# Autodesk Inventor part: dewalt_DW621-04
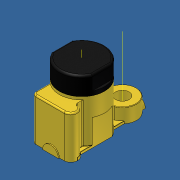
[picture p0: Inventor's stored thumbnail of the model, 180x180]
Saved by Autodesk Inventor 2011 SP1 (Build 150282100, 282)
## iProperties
Created: 2011-02
Part Number: dewalt_DW621-04
Material: Kst - PA6.6(Nylon)
Catalog Web Link: www.mittelmeyer.de
Document SubType Name: Modellieren
Designer: TMT
Manufacturer: Standard
Standards Organization: Custom
Density: 1.13 g/cm^3
Author: TMT
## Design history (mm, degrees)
sketch "Skizze2"
  geometry: L1 (-40.5, 85)-(40.5, 85); L2 (40.5, 85)-(40.5, -85); L3 (40.5, -85)-(-40.5, -85); L4 (-40.5, -85)-(-40.5, 85); L5 (0, -119)-(0, 119) reference; L6 (-56.7, 0)-(56.7, 0) reference
  constraints: 8 end point, 2 parallel, 1 horizontal, 1 perpendicular, 2 other
  dimensions: "d4" = 170 distance of L3.end L1.start (= laenge_01); "d5" = 81 distance of L2.end L3.end (= breite_01)
extrude "Extrusion2" new body sketch "Skizze2" distance "d6" = 5 (= hoehe_01); taper "d7" = 0 deg
workplane "Arbeitsebene1"
sketch "Skizze3"
  geometry: L1 (-40.5, -85)-(-40.5, 85) reference; L2 (40.5, -85)-(-40.5, -85) reference; L3 (-30.223, -85)-(-30.223, -45.277); L4 (-30.223, -45.277)-(-40.5, -35); L5 (56.7, -15)-(-56.7, -15) reference; 1 further point
  constraints: 4 end point, 2 point on line, 1 perpendicular
  dimensions: "d8" = 10.27713 distance between parallel lines of L3 L1; "d9" = 45 deg angle of L4 L2; "d11" = 20 distance from line of L4.end L5
extrude "Extrusion3" cut sketch "Skizze3" stored distance "d12" = 42.5; taper "d13" = 0 deg
sketch "Skizze4"
  geometry: L1 (40.5, -85)-(47.5, -85); L2 (47.5, -85)-(47.5, -59); L3 (47.5, -59)-(40.5, -59); L4 (40.5, -59)-(40.5, -85); 1 further point
  constraints: 8 end point, 2 parallel, 1 horizontal, 1 perpendicular
  dimensions: "d14" = 7 distance of L1.start L1.end; "d15" = 26 distance of L1.end L2.end
extrude "Extrusion4" join sketch "Skizze4" stored distance "d16" = 10; taper "d17" = 0 deg
fillet "Rundung3" dims "d18" = 13
fillet "Rundung4" dims "d19" = 8
sketch "Skizze5"
  geometry: L1 (40.5, 85)-(40.5, -59) reference; L2 (-40.5, 85)-(40.5, 85) reference; L3 (-40.5, -35)-(-30.223, -45.277) reference; L4 (30.5, 85)-(30.5, 15); L5 (30.5, 15)-(40.5, 5); L6 (65.1, -15)-(-58.1, -15) reference; 1 further point
  constraints: 4 end point, 2 parallel, 2 point on line
  dimensions: "d20" = 45 deg angle of L5 L2 (derived); "d21" = 20 distance from line of L5.end L6; "d22" = 10 distance between parallel lines of L1 L4
extrude "Extrusion5" cut sketch "Skizze5" stored distance "d23" = 30.25; taper "d24" = 0 deg
sketch "Skizze6"
  geometry: L1 (-40.5, 85)-(30.5, 85) reference; L2 (65.1, -15)-(-58.1, -15) reference; L3 (0, -119)-(0, 119) reference; C1 r 28 at (9, 57); 1 further point
  constraints: 1 centre point, 1 tangent
  dimensions: "d25" = 72 distance from line of C1.centre L2; "d26" = 9 distance from line of L3 C1.centre
extrude "Extrusion6" join sketch "Skizze6" stored distance "d27" = 3.75; taper "d28" = 0 deg
sketch "Skizze7"
  geometry: L1 (-40.5, 85)-(30.5, 85) reference; L2 (-40.5, -35)-(-40.5, 85) reference; L3 (-30.223, -45.277)-(-30.223, -77) reference; L4 (40.5, 5)-(30.5, 15) reference; L5 (-40.5, 5)-(-30.223, 15.277); L6 (-30.223, 15.277)-(-30.223, 85); 1 further point
  constraints: 4 end point, 2 perpendicular, 2 point on line, 1 collinear
  dimensions: "d29" = 45 deg angle of L5 L1 (derived); "d30" = 40 distance of L5.start L2.start
extrude "Extrusion7" cut sketch "Skizze7" stored distance "d31" = 42.75; taper "d32" = 0 deg
sketch "Skizze8"
  geometry: L1 (-30.223, 15.277)-(-40.5, 5) reference; L2 (-40.5, -35)-(-40.5, 5) reference; L3 (30.5, 74.937)-(30.5, 85) reference; L4 (-30.223, 85)-(-30.223, 15.277) reference; L5 (-37.5, 8)-(-44.813, 41.204); L6 (-38.721, 50.738)-(-30.223, 52.609); L7 (-45, 42.925)-(-45, 106.002); L8 (37, 57)-(37, 122.341); A1 r 28 centre (9, 57) between (30.5, 39.063) and (30.5, 74.937) reference; A2 r 8 centre (-37, 42.925) between (-38.721, 50.738) and (-44.813, 41.204); 1 further point
  constraints: 8 end point, 4 point on circle, 4 tangent, 2 parallel, 2 point on line, 1 centre point, 1 perpendicular
  dimensions: "d34" = 8 radius of A2; "d35" = 82 distance between parallel lines of L8 L7; "d36" = 3 distance from line of L5.start L2; "d37" = 42 distance from line of L5.start L6
extrude "Extrusion8" join sketch "Skizze8" stored distance "d38" = 3.75; taper "d39" = 0 deg
sketch "Skizze9"
  geometry: L1 (30.5, 74.937)-(30.5, 85) reference; L2 (-30.223, 85)-(30.5, 85) reference; L3 (9, 85)-(30.5, 85); L4 (30.5, 85)-(30.5, 74.937); A1 r 28 centre (9, 57) between (30.5, 39.063) and (30.5, 74.937) reference; A2 r 28 centre (9, 57) between (30.5, 74.937) and (9, 85); 1 further point
  constraints: 4 end point, 2 collinear, 2 point on circle, 1 centre point, 1 coincident, 1 tangent
extrude "Extrusion9" cut sketch "Skizze9" stored distance "d40" = 31.25; taper "d41" = 0 deg
sketch "Skizze20"
  geometry: L1 (-37.5, 8)-(-40.5, 5) reference; L2 (-40.5, -35)-(-40.5, 5) reference; L3 (-40.5, -35)-(-30.223, -45.277) reference; L4 (40.5, 5)-(40.5, -59) reference; L5 (66, -15)-(-63.5, -15) reference; L6 (-40.5, -15)-(40.5, -15); A1 r 45.169 centre (0, -15) between (-40.5, -35) and (40.5, -35); A2 r 45.169 centre (0, -15) between (40.5, 5) and (-40.5, 5); 1 further point
  constraints: 6 point on line, 5 point on circle, 3 end point, 2 centre point, 2 midpoint
extrude "Extrusion15" join sketch "Skizze20" stored distance "d87" = 10; taper "d88" = 0 deg
sketch "Skizze21"
  geometry: 1 further point
sketch "Skizze22"
  geometry: A1 r 45.169 centre (0, -15) between (-40.5, -35) and (-30.223, -48.568) reference; 2 further points
  constraints: 1 coincident, 3 other
extrude "Extrusion16" join sketch "Skizze22" distance "d89" = 90; taper "d90" = 0 deg
sketch "Skizze23"
  geometry: C1 r 45.169 at (0, 0) reference; 1 further point
extrude "Extrusion17" join sketch "Skizze23" distance "d91" = 32; taper "d92" = 0 deg
sketch "Skizze24"
  geometry: L1 (40.5, 20)-(40.5, -44) reference; L2 (-40.5, -20)-(-40.5, 20) reference; L3 (40.5, 20)-(40.5, -20); A1 r 45.169 centre (0, 0) between (40.5, 20) and (-40.5, -20) reference; 1 further point
  constraints: 2 end point, 1 point on circle, 1 point on line
extrude "Extrusion18" cut sketch "Skizze24" distance "d93" = 28; taper "d94" = 0 deg
sketch "Skizze25"
  geometry: L1 (-40.5, 5)-(-40.5, -35) reference; L2 (40.5, -35)-(40.5, 5) reference; A1 r 45.169 centre (0, -15) between (-40.5, 5) and (-40.5, -35) reference; A2 r 45.169 centre (0, -15) between (40.5, -35) and (40.5, 5) reference; 1 further point
extrude "Extrusion19" cut sketch "Skizze25" distance "d95" = 48; taper "d96" = 0 deg
sketch "Skizze26"
  geometry: L1 (-30.223, -48.568)-(-30.223, -77) reference; L2 (34.5, -85)-(-22.223, -85) reference; L3 (40.5, -35)-(40.5, -59) reference; L4 (32.5, -46.369)-(32.5, -59.155); A1 r 45.169 centre (0, -15) between (-30.223, -48.568) and (40.5, -35) reference; A2 r 8 centre (-22.223, -77) between (-30.223, -77) and (-22.223, -85) reference; A3 r 13 centre (34.5, -72) between (34.5, -85) and (47.5, -72) reference; A4 r 13 centre (34.5, -72) between (34.5, -85) and (32.5, -59.155); 1 further point
  constraints: 3 end point, 3 point on circle, 1 centre point, 1 coincident, 1 parallel
  dimensions: "d97" = 8 distance between parallel lines of L3 L4
extrude "Extrusion20" join sketch "Skizze26" distance "d98" = 80; taper "d99" = 0 deg
sketch "Skizze27"
  geometry: L1 (-30.223, 85)-(-30.223, 52.609) reference; L2 (-1.392, 31)-(19.392, 31); A1 r 28 centre (9, 57) between (30.5, 39.063) and (9, 85) reference; A2 r 28 centre (9, 57) between (19.392, 31) and (-1.392, 31); 1 further point
  constraints: 2 end point, 2 point on circle, 1 centre point, 1 coincident, 1 concentric, 1 perpendicular
  dimensions: "d100" = 26 distance from line of L2 A2.centre
extrude "Extrusion21" join sketch "Skizze27" distance "d101" = 24; taper "d102" = 0 deg
sketch "Skizze28"
  geometry: L1 (-30.223, 52.609)-(-38.721, 50.738) reference; L2 (-44.813, 41.204)-(-37.86, 9.635) reference; 2 further points
  dimensions: "d103" = 14 distance from line of point (-29.85, 38.356) L2; "d104" = 14 distance from line of point (-29.85, 38.356) L1
hole "Hole4" sketch "Skizze28" at (-29.85, 38.356) diameter "d105" = 12; stored, may be unused: countersink angle "d109" = 90 deg, drill point angle "d111" = 118 deg; dims "d106" = 6, "d107" = 4, "d108" = 2, "d110" = 8
workaxis "Arbeitsachse1"
sketch "Skizze29"
  geometry: L1 (-4.669, 99)-(-4.669, 53) reference; L2 (-4.669, 91.268)-(-3.669, 91); L3 (-3.669, 91)-(-4.669, 90.732); L4 (-3.669, 91)-(-4.669, 91); L5 (0, 127)-(81, 127) reference; L6 (40.5, 152.4)-(40.5, -25.4) reference; 1 further point
  constraints: 6 end point, 3 point on line, 1 perpendicular, 1 other
  dimensions: "d112" = 30 deg angle of L3 L2; "d113" = 1 distance from line of L1 L2.end; "d114" = 36 distance between parallel lines of L4 L5
revolve "Umdrehung1" sketch "Skizze29" stored, may be unused: angle "d115" = 90 deg
fillet "Rundung7" dims "d116" = 4
sketch "Skizze30"
  geometry: A1 r 28 centre (9, 57) between (19.392, 31) and (-1.392, 31) reference; 1 further point
hole "Hole5" sketch "Skizze30" at (9, 57) diameter "d117" = 27; stored, may be unused: countersink angle "d121" = 90 deg, drill point angle "d123" = 118 deg; dims "d118" = 6, "d119" = 4, "d120" = 2, "d122" = 8
workaxis "Arbeitsachse2"
sketch "Skizze31"
  geometry: L1 (-39.223, 5)-(0, 5) reference; L2 (28, 5)-(0, 5) reference; L3 (0, -147.4)-(0, 30.4) reference; A1 r 16 centre (0, 5) between (-16, 5) and (16, 5); 2 further points
  constraints: 2 point on circle, 2 point on line, 1 centre point, 1 coincident
  dimensions: "d124" = 32 diameter of A1
extrude "Extrusion22" join sketch "Skizze31" distance "d125" = 2; taper "d127" = 0 deg; dims "d126" = 6, "d128" = 0
sketch "Skizze32"
  geometry: L1 (56.723, 0)-(0, 0) reference; A1 r 16 centre (31.223, 0) between (47.223, 0) and (15.223, 0) reference; 1 further point
extrude "Extrusion23" join sketch "Skizze32" distance "d129" = 2; taper "d130" = 0 deg
fillet "Rundung8" dims "d131" = 0.5
fillet "Rundung9" dims "d132" = 0.5
fillet "Rundung10" dims "d133" = 1
fillet "Rundung11" dims "d134" = 3
fillet "Rundung12" dims "d135" = 3
fillet "Rundung13" dims "d136" = 0.5
fillet "Rundung14" dims "d137" = 0.5
fillet "Rundung15" dims "d138" = 0.5
sketch "Skizze33"
  geometry: L1 (38.721, 50.738)-(30.223, 52.609) reference; L2 (30.223, 52.609)-(30.223, 85) reference; L3 (30.223, 85)-(7.5, 85) reference; L4 (7.067, 85.25)-(25.284, 53.697); L5 (30.223, 52.609)-(25.284, 53.697); L6 (0, -122.631)-(0, 121.938) reference; A1 r 0.5 centre (7.5, 85.5) between (7, 85.5) and (7.5, 85) reference; 1 further point
  constraints: 4 end point, 1 collinear, 1 point on circle, 1 tangent
  dimensions: "d139" = 30 deg angle of L4 L6
extrude "Extrusion24" cut sketch "Skizze33" stored distance "d140" = 16.5; taper "d141" = 0 deg
fillet "Rundung16" dims "d142" = 0.5
node "Volumenkörper1"
node "Volumenkörpern"
node "Oberflächenkörpern"
node "Projizierte Kontur1"
other parameters: "laenge_01" = 170 [user parameter; used in 1 equation term], "breite_01" = 81 [user parameter; used in 1 equation term], "hoehe_01" = 5 [user parameter; used in 1 equation term]
